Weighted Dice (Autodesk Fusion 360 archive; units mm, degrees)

design "Weighted Dice" references "Hollow Cut"
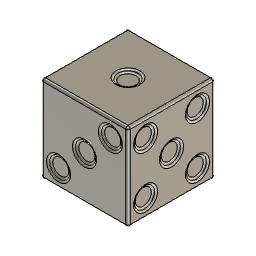
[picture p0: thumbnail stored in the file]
part number: 2025-09-26-16-34-02-084
sketch "Sketch1" plane through (0, 0, 0) normal (0, 0, 1) x axis (1, 0, 0)
  line L1 (19, 0) -> (0, 0)
  line L2 (19, 19) -> (19, 0)
  line L3 (0, 19) -> (19, 19)
  line L4 (0, 0) -> (0, 19)
  point P1 (0, 0)
  point P2 (0, 0)
  point P3 (19, 0)
  point P5 (0, 19)
  horizontal L1
  vertical L2
  horizontal L3
  vertical L4
  coincident P1 P2
  dimension "d1" distance P2 P3 = 19
  dimension "d2" distance P2 P5 = 19
extrude "Extrude1" new body sketch "Sketch1" along normal blind 19
sketch "Sketch2" plane through (0, 0, 19) normal (0, 0, 1) x axis (-1, 0, 0)
  line L1 (0, 0) -> (0, -19)
  line L2 (-19, 0) -> (0, 0)
  line L3 (-19, -19) -> (-19, 0)
  line L4 (0, -19) -> (-19, -19)
  line L5 (-19, -9.5) -> (0, -9.5)
  line L6 (-9.5, 0) -> (-9.5, -19)
  circle C1 centre (-9.5, -9.5) radius 2.25
  point P6 (0, -9.5)
  point P7 (-19, -9.5)
  point P8 (-9.5, -19)
  point P9 (-9.5, 0)
  point P10 (-9.5, -9.5)
  midpoint L1 P6
  midpoint L3 P7
  midpoint L4 P8
  midpoint L2 P9
  midpoint L5 P10
  dimension "d6" diameter C1 = 4.5
sketch "Sketch3" plane through (0, 0, 0) normal (0, 0, -1) x axis (1, 0, 0)
  line L1 (0, -19) -> (0, 0)
  line L2 (19, -19) -> (0, -19)
  line L3 (19, 0) -> (19, -19)
  line L4 (0, 0) -> (19, 0)
  line L5 (0, -15.1569) -> (3.8431, -15.1569)
  line L6 (3.8431, -19) -> (3.8431, -15.1569)
  line L7 (19, -15.1569) -> (15.1569, -15.1569)
  line L8 (15.1569, -19) -> (15.1569, -15.1569)
  line L9 (19, -3.8431) -> (15.1569, -3.8431)
  line L10 (15.1569, 0) -> (15.1569, -3.8431)
  line L11 (3.8431, 0) -> (3.8431, -3.8431)
  line L12 (0, -3.8431) -> (3.8431, -3.8431)
  line L13 (0, -9.5) -> (3.8431, -9.5)
  line L14 (19, -9.5) -> (15.1569, -9.5)
  line L15 (3.8431, -9.5) -> (3.8431, -3.8431)
  line L16 (3.8431, -9.5) -> (3.8431, -15.1569)
  line L17 (15.1569, -9.5) -> (15.1569, -3.8431)
  line L18 (15.1569, -9.5) -> (15.1569, -15.1569)
  circle C1 centre (3.8431, -3.8431) radius 2.25
  circle C2 centre (3.8431, -9.5) radius 2.25
  circle C3 centre (3.8431, -15.1569) radius 2.25
  circle C4 centre (15.1569, -3.8431) radius 2.25
  circle C5 centre (15.1569, -9.5) radius 2.25
  circle C6 centre (15.1569, -15.1569) radius 2.25
  point P8 (3.8431, -15.1569)
  point P13 (3.8431, -15.1569)
  point P14 (0, -15.1569)
  point P15 (3.8431, -15.1569)
  point P16 (3.8431, -19)
  point P11 (15.1569, -15.1569)
  point P17 (15.1569, -15.1569)
  point P18 (19, -15.1569)
  point P19 (15.1569, -15.1569)
  point P20 (15.1569, -19)
  point P9 (15.1569, -3.8431)
  point P21 (15.1569, -3.8431)
  point P22 (19, -3.8431)
  point P23 (15.1569, -3.8431)
  point P24 (15.1569, 0)
  point P6 (3.8431, -3.8431)
  point P25 (3.8431, -3.8431)
  point P26 (3.8431, 0)
  point P27 (3.8431, -3.8431)
  point P28 (0, -3.8431)
  point P7 (3.8431, -9.5)
  point P29 (3.8431, -9.5)
  point P30 (0, -9.5)
  point P10 (15.1569, -9.5)
  point P31 (15.1569, -9.5)
  point P32 (19, -9.5)
  point P33 (3.8431, -3.8431)
  point P34 (3.8431, -9.5)
  point P35 (3.8431, -15.1569)
  point P36 (3.8431, -9.5)
  point P37 (15.1569, -3.8431)
  point P38 (15.1569, -9.5)
  point P39 (15.1569, -15.1569)
  point P40 (15.1569, -9.5)
  point P12 (9.5, -9.5)
  coincident P8 P13
  coincident L1 P14
  perpendicular L1 L5
  coincident P8 P15
  coincident L2 P16
  perpendicular L2 L6
  coincident P11 P17
  coincident L3 P18
  perpendicular L3 L7
  coincident P11 P19
  coincident L2 P20
  perpendicular L2 L8
  coincident P9 P21
  coincident L3 P22
  perpendicular L3 L9
  coincident P9 P23
  coincident L4 P24
  perpendicular L4 L10
  coincident P6 P25
  coincident L4 P26
  perpendicular L4 L11
  coincident P6 P27
  coincident L1 P28
  perpendicular L1 L12
  equal L11 L12
  equal L9 L10
  equal L7 L8
  equal L5 L6
  coincident P7 P29
  coincident L1 P30
  perpendicular L1 L13
  coincident P10 P31
  coincident L3 P32
  perpendicular L3 L14
  equal L9 L14
  equal L12 L13
  coincident P6 P33
  coincident P7 P34
  coincident P8 P35
  coincident P7 P36
  coincident P9 P37
  coincident P10 P38
  coincident P11 P39
  coincident P10 P40
  equal L17 L18
  equal L15 L16
  dimension "d7" diameter C1 = 4.5
  dimension "d8" diameter C2 = 4.5
  dimension "d9" diameter C3 = 4.5
  dimension "d10" diameter C4 = 4.5
  dimension "d11" diameter C5 = 4.5
  dimension "d12" diameter C6 = 4.5
  dimension "d38" distance P6 P12 = 8
  dimension "d39" distance P8 P12 = 8
  dimension "d40" distance P9 P12 = 8
  dimension "d41" distance P11 P12 = 8
sketch "Sketch4" plane through (0, 0, 0) normal (-1, 0, 0) x axis (0, -1, 0)
  line L1 (0, 0) -> (-19, 0)
  line L2 (0, 19) -> (0, 0)
  line L3 (-19, 19) -> (0, 19)
  line L4 (-19, 0) -> (-19, 19)
  line L5 (0, 15.1569) -> (-3.8431, 15.1569)
  line L6 (-3.8431, 19) -> (-3.8431, 15.1569)
  line L7 (-19, 9.5) -> (0, 9.5)
  line L8 (-9.5, 0) -> (-9.5, 19)
  line L9 (-19, 3.8431) -> (-15.1569, 3.8431)
  line L10 (-15.1569, 0) -> (-15.1569, 3.8431)
  circle C1 centre (-3.8431, 15.1569) radius 2.25
  circle C2 centre (-15.1569, 3.8431) radius 2.25
  point P6 (-3.8431, 15.1569)
  point P8 (-3.8431, 15.1569)
  point P9 (0, 15.1569)
  point P10 (-3.8431, 15.1569)
  point P11 (-3.8431, 19)
  point P12 (0, 9.5)
  point P13 (-19, 9.5)
  point P14 (-9.5, 19)
  point P15 (-9.5, 0)
  point P7 (-15.1569, 3.8431)
  point P16 (-15.1569, 3.8431)
  point P17 (-19, 3.8431)
  point P18 (-15.1569, 3.8431)
  point P19 (-15.1569, 0)
  point P20 (-9.5, 9.5)
  coincident P6 P8
  coincident L2 P9
  perpendicular L2 L5
  coincident P6 P10
  coincident L3 P11
  perpendicular L3 L6
  midpoint L2 P12
  midpoint L4 P13
  midpoint L3 P14
  midpoint L1 P15
  coincident P7 P16
  coincident L4 P17
  perpendicular L4 L9
  coincident P7 P18
  coincident L1 P19
  perpendicular L1 L10
  equal L5 L6
  equal L9 L10
  midpoint L8 P20
  dimension "d13" diameter C1 = 4.5
  dimension "d14" diameter C2 = 4.5
  dimension "d43" distance P6 P20 = 8
  dimension "d44" distance P7 P20 = 8
sketch "Sketch5" plane through (0, 0, 0) normal (0, -1, 0) x axis (1, 0, 0)
  line L1 (19, 0) -> (0, 0)
  line L2 (19, 19) -> (19, 0)
  line L3 (0, 19) -> (19, 19)
  line L4 (0, 0) -> (0, 19)
  line L5 (19, 9.5) -> (0, 9.5)
  line L6 (9.5, 0) -> (9.5, 19)
  line L7 (0, 19) -> (0, 0)
  line L8 (3.8431, 0) -> (3.8431, 3.8431)
  line L9 (0, 3.8431) -> (3.8431, 3.8431)
  line L10 (15.1569, 19) -> (15.1569, 15.1569)
  line L11 (19, 15.1569) -> (15.1569, 15.1569)
  circle C1 centre (9.5, 9.5) radius 2.25
  circle C2 centre (15.1569, 15.1569) radius 2.25
  circle C3 centre (3.8431, 3.8431) radius 2.25
  point P6 (0, 9.5)
  point P7 (19, 9.5)
  point P8 (9.5, 19)
  point P9 (9.5, 0)
  point P10 (9.5, 9.5)
  point P12 (3.8431, 3.8431)
  point P15 (3.8431, 3.8431)
  point P16 (3.8431, 0)
  point P17 (3.8431, 3.8431)
  point P18 (0, 3.8431)
  point P11 (15.1569, 15.1569)
  point P19 (15.1569, 15.1569)
  point P20 (15.1569, 19)
  point P21 (15.1569, 15.1569)
  point P22 (19, 15.1569)
  midpoint L4 P6
  midpoint L2 P7
  midpoint L3 P8
  midpoint L1 P9
  midpoint L5 P10
  coincident P12 P15
  coincident L1 P16
  perpendicular L1 L8
  coincident P12 P17
  coincident L4 P18
  perpendicular L4 L9
  equal L8 L9
  coincident P11 P19
  coincident L3 P20
  perpendicular L3 L10
  coincident P11 P21
  coincident L2 P22
  perpendicular L2 L11
  equal L10 L11
  dimension "d15" diameter C1 = 4.5
  dimension "d16" diameter C2 = 4.5
  dimension "d17" diameter C3 = 4.5
  dimension "d27" distance P10 P12 = 8
  dimension "d28" distance P10 P11 = 8
  dimension "d29" distance P10 L7 = 9.5
sketch "Sketch6" plane through (19, 0, 0) normal (1, 0, 0) x axis (0, 1, 0)
  line L1 (19, 0) -> (0, 0)
  line L2 (19, 19) -> (19, 0)
  line L3 (0, 19) -> (19, 19)
  line L4 (0, 0) -> (0, 19)
  line L5 (19, 9.5) -> (0, 9.5)
  line L6 (9.5, 0) -> (9.5, 19)
  line L7 (0, 12.9069) -> (0, 17.4069)
  line L8 (0, 19) -> (19, 19)
  line L9 (3.8431, 19) -> (3.8431, 15.1569)
  line L10 (0, 15.1569) -> (3.8431, 15.1569)
  line L11 (15.1569, 19) -> (15.1569, 15.1569)
  line L12 (19, 15.1569) -> (15.1569, 15.1569)
  line L13 (0, 3.8431) -> (3.8431, 3.8431)
  line L14 (3.8431, 0) -> (3.8431, 3.8431)
  line L15 (19, 3.8431) -> (15.1569, 3.8431)
  line L16 (15.1569, 0) -> (15.1569, 3.8431)
  circle C1 centre (9.5, 9.5) radius 2.25
  circle C2 centre (3.8431, 15.1569) radius 2.25
  circle C3 centre (3.8431, 3.8431) radius 2.25
  circle C4 centre (15.1569, 15.1569) radius 2.25
  circle C5 centre (15.1569, 3.8431) radius 2.25
  point P6 (0, 9.5)
  point P7 (19, 9.5)
  point P8 (9.5, 19)
  point P9 (9.5, 0)
  point P10 (9.5, 9.5)
  point P11 (3.8431, 15.1569)
  point P19 (3.8431, 15.1569)
  point P20 (3.8431, 19)
  point P21 (3.8431, 15.1569)
  point P22 (0, 15.1569)
  point P13 (15.1569, 15.1569)
  point P23 (15.1569, 15.1569)
  point P24 (15.1569, 19)
  point P25 (15.1569, 15.1569)
  point P26 (19, 15.1569)
  point P12 (3.8431, 3.8431)
  point P27 (3.8431, 3.8431)
  point P28 (0, 3.8431)
  point P29 (3.8431, 3.8431)
  point P30 (3.8431, 0)
  point P14 (15.1569, 3.8431)
  point P31 (15.1569, 3.8431)
  point P32 (19, 3.8431)
  point P33 (15.1569, 3.8431)
  point P34 (15.1569, 0)
  midpoint L4 P6
  midpoint L2 P7
  midpoint L3 P8
  midpoint L1 P9
  midpoint L6 P10
  coincident P11 P19
  coincident L8 P20
  perpendicular L8 L9
  coincident P11 P21
  equal L9 L10
  coincident L7 P22
  coincident P13 P23
  coincident L8 P24
  perpendicular L8 L11
  coincident P13 P25
  coincident L2 P26
  perpendicular L2 L12
  equal L11 L12
  coincident P12 P27
  coincident L4 P28
  perpendicular L4 L13
  coincident P12 P29
  coincident L1 P30
  perpendicular L1 L14
  equal L13 L14
  coincident P14 P31
  coincident L2 P32
  perpendicular L2 L15
  coincident P14 P33
  coincident L1 P34
  perpendicular L1 L16
  equal L15 L16
  dimension "d18" diameter C1 = 4.5
  dimension "d19" diameter C2 = 4.5
  dimension "d20" diameter C3 = 4.5
  dimension "d21" diameter C4 = 4.5
  dimension "d22" diameter C5 = 4.5
  dimension "d30" distance P10 P11 = 8
  dimension "d31" distance P10 P13 = 8
  dimension "d32" distance P10 P14 = 8
  dimension "d33" distance P10 P12 = 8
  dimension "d37" angle L9 L10 = 90
sketch "Sketch7" plane through (0, 19, 0) normal (0, 1, 0) x axis (-1, 0, 0)
  line L1 (0, 0) -> (-19, 0)
  line L2 (0, 19) -> (0, 0)
  line L3 (-19, 19) -> (0, 19)
  line L4 (-19, 0) -> (-19, 19)
  line L5 (-15.1569, 0) -> (-15.1569, 3.8431)
  line L6 (-19, 3.8431) -> (-15.1569, 3.8431)
  line L7 (0, 9.5) -> (-19, 9.5)
  line L8 (-9.5, 0) -> (-9.5, 19)
  line L9 (-15.1569, 19) -> (-15.1569, 15.1569)
  line L10 (-19, 15.1569) -> (-15.1569, 15.1569)
  line L11 (0, 15.1569) -> (-3.8431, 15.1569)
  line L12 (-3.8431, 19) -> (-3.8431, 15.1569)
  line L13 (0, 3.8431) -> (-3.8431, 3.8431)
  line L14 (-3.8431, 0) -> (-3.8431, 3.8431)
  circle C1 centre (-15.1569, 15.1569) radius 2.25
  circle C2 centre (-15.1569, 3.8431) radius 2.25
  circle C3 centre (-3.8431, 15.1569) radius 2.25
  circle C4 centre (-3.8431, 3.8431) radius 2.25
  point P7 (-15.1569, 3.8431)
  point P11 (-15.1569, 3.8431)
  point P12 (-15.1569, 0)
  point P13 (-15.1569, 3.8431)
  point P14 (-19, 3.8431)
  point P15 (-19, 9.5)
  point P16 (0, 9.5)
  point P17 (-9.5, 19)
  point P18 (-9.5, 0)
  point P6 (-15.1569, 15.1569)
  point P19 (-15.1569, 15.1569)
  point P20 (-15.1569, 19)
  point P21 (-15.1569, 15.1569)
  point P22 (-19, 15.1569)
  point P8 (-3.8431, 15.1569)
  point P23 (-3.8431, 15.1569)
  point P24 (0, 15.1569)
  point P25 (-3.8431, 15.1569)
  point P26 (-3.8431, 19)
  point P9 (-3.8431, 3.8431)
  point P27 (-3.8431, 3.8431)
  point P28 (0, 3.8431)
  point P29 (-3.8431, 3.8431)
  point P30 (-3.8431, 0)
  point P10 (-9.5, 9.5)
  coincident P7 P11
  coincident L1 P12
  perpendicular L1 L5
  coincident P7 P13
  coincident L4 P14
  perpendicular L4 L6
  midpoint L4 P15
  midpoint L2 P16
  midpoint L3 P17
  midpoint L1 P18
  equal L5 L6
  coincident P6 P19
  coincident L3 P20
  perpendicular L3 L9
  coincident P6 P21
  coincident L4 P22
  perpendicular L4 L10
  equal L9 L10
  coincident P8 P23
  coincident L2 P24
  perpendicular L2 L11
  coincident P8 P25
  coincident L3 P26
  perpendicular L3 L12
  equal L11 L12
  coincident P9 P27
  coincident L2 P28
  perpendicular L2 L13
  coincident P9 P29
  coincident L1 P30
  perpendicular L1 L14
  equal L13 L14
  dimension "d23" diameter C1 = 4.5
  dimension "d24" diameter C2 = 4.5
  dimension "d25" diameter C3 = 4.5
  dimension "d26" diameter C4 = 4.5
  dimension "d45" distance P6 P10 = 8
  dimension "d46" distance P7 P10 = 8
  dimension "d48" distance P8 P10 = 8
  dimension "d78" distance P9 P10 = 8
extrude "Extrude2" cut sketch "Sketch2" profile of C1 against normal blind 0.5
fillet "Fillet1" radius 0.5
extrude "Extrude3" cut sketch "Sketch6" profile of C1 C2 C3 C4 C5 against normal blind 0.5
fillet "Fillet2" radius 0.5
extrude "Extrude4" cut sketch "Sketch7" profile of C1 C2 C3 C4 against normal blind 0.5
fillet "Fillet3" radius 0.5
extrude "Extrude5" cut sketch "Sketch4" profile of C1 C2 against normal blind 0.5
fillet "Fillet4" radius 0.5
extrude "Extrude6" cut sketch "Sketch5" profile of C1 C2 C3 against normal blind 0.5
fillet "Fillet5" radius 0.5
extrude "Extrude7" cut sketch "Sketch3" profile of C1 C2 C3 C4 C5 C6 against normal blind 0.5
fillet "Fillet6" radius 0.5
fillet "Fillet7" radius 0.5
fillet "Fillet8" radius 0.5
component_insert "Component Insert"
work_plane "WorkPlane1"
combine "Combine2"
work_plane "WorkPlane2"

design "Hollow Cut"
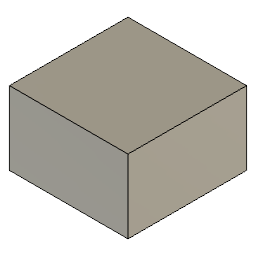
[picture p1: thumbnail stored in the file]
part number: 2025-09-27-23-07-06-343
sketch "Sketch1" plane through (0, 0, 0) normal (0, 0, 1) x axis (1, 0, 0)
  line L1 (17, 0) -> (0, 0)
  line L2 (17, 17) -> (17, 0)
  line L3 (0, 17) -> (17, 17)
  line L4 (0, 0) -> (0, 17)
  point P1 (0, 0)
  point P2 (0, 0)
  point P3 (17, 0)
  point P5 (0, 17)
  horizontal L1
  vertical L2
  horizontal L3
  vertical L4
  coincident P1 P2
  dimension "d1" distance P2 P3 = 17
  dimension "d2" distance P2 P5 = 17
extrude "Extrude1" new body sketch "Sketch1" along normal blind 10.53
